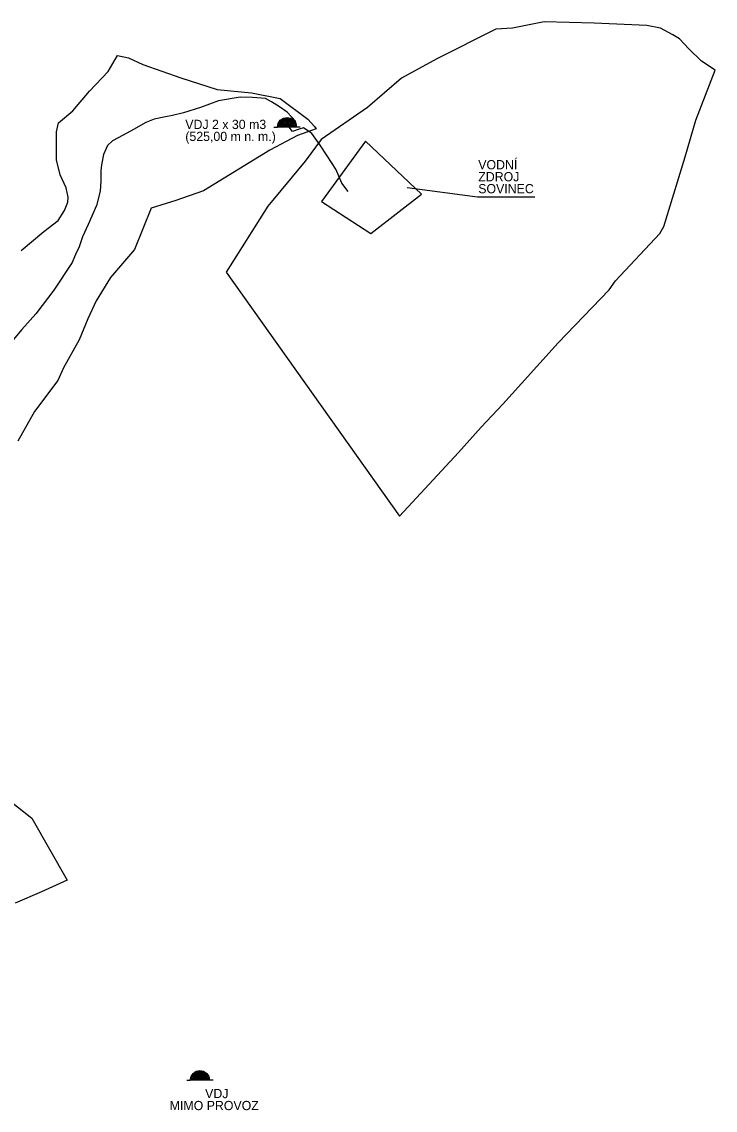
# Model space of a CAD drawing. Extents: x -547132 to -534149, y -1095664 to -1090118.
# Drawn here: x -544078 to -543326, y -1094606 to -1093426 of the extents above; entities that cross this region are included whole.
import ezdxf

# ---------------------------------------------------------------- set-up
doc = ezdxf.new("R2010")
doc.units = 0
for name, color, linetype in [('Vrstva 15', 7, 'Continuous'), ('Vrstva 3', 7, 'Continuous'), ('Vrstva 54', 7, 'Continuous'), ('Vrstva 55', 7, 'Continuous'), ('Vrstva 56', 7, 'Continuous')]:
    doc.layers.add(name, color=color, linetype=linetype)

msp = doc.modelspace()

# ---------------------------------------------------------------- linework, layer by layer
at = {"layer": 'Vrstva 15'}
for p, q in [((-543804.9, -1093540.2), (-543801, -1093540.2)), ((-543776.1, -1093540.2), (-543780.1, -1093540.2)), ((-543899.3, -1094573.8), (-543895.4, -1094573.8)), ((-543870.5, -1094573.8), (-543874.5, -1094573.8))]:
    msp.add_line(p, q, dxfattribs=at)
for points in [[(-543801, -1093540.2), (-543800.2, -1093536.2), (-543797.9, -1093532.8), (-543794.5, -1093530.6), (-543790.5, -1093529.8), (-543786.5, -1093530.6), (-543783.1, -1093532.8), (-543780.9, -1093536.2), (-543780.1, -1093540.2)], [(-543799.7, -1093539.2), (-543799.2, -1093536.6), (-543797.2, -1093533.6), (-543794.1, -1093531.5), (-543790.5, -1093530.8), (-543786.9, -1093531.5), (-543783.8, -1093533.6), (-543781.8, -1093536.6), (-543781.3, -1093539.2)], [(-543798.5, -1093538.2), (-543798.3, -1093537), (-543796.5, -1093534.3), (-543793.7, -1093532.4), (-543790.5, -1093531.8), (-543787.3, -1093532.4), (-543784.6, -1093534.3), (-543782.7, -1093537), (-543782.5, -1093538.2)], [(-543797.2, -1093537.2), (-543795.7, -1093535), (-543793.3, -1093533.4), (-543790.5, -1093532.8), (-543787.7, -1093533.4), (-543785.3, -1093535), (-543783.8, -1093537.2)], [(-543795.4, -1093536.2), (-543795, -1093535.7), (-543792.9, -1093534.3), (-543790.5, -1093533.8), (-543788.1, -1093534.3), (-543786, -1093535.7), (-543785.7, -1093536.2)], [(-543792.3, -1093535.2), (-543790.5, -1093534.9), (-543788.7, -1093535.2)], [(-543895.4, -1094573.8), (-543894.6, -1094569.8), (-543892.3, -1094566.4), (-543888.9, -1094564.2), (-543884.9, -1094563.4), (-543880.9, -1094564.2), (-543877.6, -1094566.4), (-543875.3, -1094569.8), (-543874.5, -1094573.8)], [(-543894.2, -1094572.8), (-543893.7, -1094570.2), (-543891.6, -1094567.2), (-543888.5, -1094565.1), (-543884.9, -1094564.4), (-543881.3, -1094565.1), (-543878.3, -1094567.2), (-543876.2, -1094570.2), (-543875.7, -1094572.8)], [(-543893, -1094571.8), (-543892.7, -1094570.6), (-543890.9, -1094567.9), (-543888.2, -1094566.1), (-543884.9, -1094565.4), (-543881.7, -1094566.1), (-543879, -1094567.9), (-543877.2, -1094570.6), (-543876.9, -1094571.8)], [(-543891.7, -1094570.8), (-543890.2, -1094568.6), (-543887.8, -1094567), (-543884.9, -1094566.4), (-543882.1, -1094567), (-543879.7, -1094568.6), (-543878.2, -1094570.8)], [(-543889.8, -1094569.8), (-543889.4, -1094569.3), (-543887.4, -1094567.9), (-543884.9, -1094567.5), (-543882.5, -1094567.9), (-543880.4, -1094569.3), (-543880.1, -1094569.8)], [(-543886.7, -1094568.8), (-543884.9, -1094568.5), (-543883.2, -1094568.8)]]:
    msp.add_lwpolyline(points, close=True, dxfattribs=at)
at = {"layer": 'Vrstva 3'}
for points in [[(-543783.5, -1093536.2), (-543781.1, -1093534), (-543790.2, -1093524.2), (-543798.7, -1093518.4), (-543807.5, -1093512.9), (-543814, -1093509.3), (-543827.9, -1093508.1), (-543841.3, -1093507.8), (-543864.9, -1093511.9), (-543874.6, -1093515.5), (-543884.2, -1093518.9), (-543902.9, -1093524.9), (-543914.7, -1093527.8), (-543922.4, -1093529), (-543934.4, -1093531.6), (-543943.7, -1093535.4), (-543957, -1093542.7), (-543968.2, -1093548.9), (-543979.9, -1093555.3), (-543985, -1093560.3), (-543989.5, -1093570.1), (-543991.7, -1093581.3), (-543992.2, -1093587.6), (-543992.2, -1093598.8), (-543993, -1093609.7), (-543997.2, -1093625.1), (-544006.2, -1093645.7), (-544012.1, -1093659.4), (-544016.2, -1093671.3), (-544019, -1093676.5), (-544023.4, -1093687.2), (-544043.3, -1093716.9), (-544062.7, -1093742.9), (-544078.1, -1093759.8)], [(-543783.5, -1093536.2), (-543781.1, -1093534), (-543790.2, -1093524.2), (-543798.7, -1093518.4), (-543807.5, -1093512.9), (-543814, -1093509.3), (-543827.9, -1093508.1), (-543841.3, -1093507.8), (-543864.9, -1093511.9), (-543874.6, -1093515.5), (-543884.2, -1093518.9), (-543902.9, -1093524.9), (-543914.7, -1093527.8), (-543922.4, -1093529), (-543934.4, -1093531.6), (-543943.7, -1093535.4), (-543957, -1093542.7), (-543968.2, -1093548.9), (-543979.9, -1093555.3), (-543985, -1093560.3), (-543989.5, -1093570.1), (-543991.7, -1093581.3), (-543992.2, -1093587.6), (-543992.2, -1093598.8), (-543993, -1093609.7), (-543997.2, -1093625.1), (-544006.2, -1093645.7), (-544012.1, -1093659.4), (-544016.2, -1093671.3), (-544019, -1093676.5), (-544023.4, -1093687.2), (-544043.3, -1093716.9), (-544062.7, -1093742.9), (-544078.1, -1093759.8)], [(-543724.3, -1093610.2), (-543731, -1093601.2), (-543737.6, -1093586), (-543746.9, -1093571.3), (-543754.6, -1093559.7), (-543763.5, -1093547), (-543772.6, -1093541), (-543777.5, -1093542.3), (-543784.6, -1093545.1), (-543788.1, -1093540.3)], [(-543724.3, -1093610.2), (-543731, -1093601.2), (-543737.6, -1093586), (-543746.9, -1093571.3), (-543754.6, -1093559.7), (-543763.5, -1093547), (-543772.6, -1093541), (-543777.5, -1093542.3), (-543784.6, -1093545.1), (-543788.1, -1093540.3)], [(-544078.1, -1093759.8), (-544096.7, -1093782), (-544120.8, -1093818.9), (-544135.7, -1093837.7), (-544160.8, -1093868.2), (-544170, -1093877.9), (-544188.5, -1093891.9), (-544202.8, -1093903.2), (-544216.3, -1093916.1), (-544238.9, -1093943.2), (-544254, -1093962.7), (-544263.4, -1093977.3), (-544284.6, -1094008), (-544299.8, -1094026.6), (-544307.5, -1094035.3), (-544316.2, -1094045.5), (-544341.9, -1094072.9), (-544346.8, -1094078.5)], [(-544078.1, -1093759.8), (-544096.7, -1093782), (-544120.8, -1093818.9), (-544135.7, -1093837.7), (-544160.8, -1093868.2), (-544170, -1093877.9), (-544188.5, -1093891.9), (-544202.8, -1093903.2), (-544216.3, -1093916.1), (-544238.9, -1093943.2), (-544254, -1093962.7), (-544263.4, -1093977.3), (-544284.6, -1094008), (-544299.8, -1094026.6), (-544307.5, -1094035.3), (-544316.2, -1094045.5), (-544341.9, -1094072.9), (-544346.8, -1094078.5)]]:
    msp.add_lwpolyline(points, dxfattribs=at)
at = {"layer": 'Vrstva 54'}
for points in [[(-544078.6, -1093674), (-544054.1, -1093653.3), (-544038.8, -1093641.5), (-544031.7, -1093630.7), (-544028.1, -1093621.6), (-544027.9, -1093616.1), (-544030, -1093606.1), (-544036.4, -1093592.1), (-544040.5, -1093575.9), (-544040.5, -1093545.4), (-544038.2, -1093535.6), (-544022.6, -1093522.7), (-544004.6, -1093501.3), (-543984.3, -1093480), (-543974.3, -1093462.4), (-543962.2, -1093465.1), (-543946.7, -1093472.4), (-543905.7, -1093486.8), (-543866.3, -1093499.4), (-543829.2, -1093503.2), (-543797.9, -1093509.3), (-543767.8, -1093531.6), (-543760.7, -1093539.4), (-543759, -1093542), (-543779.2, -1093549.2), (-543809.3, -1093565.4), (-543880.9, -1093609.5), (-543911.2, -1093619.7), (-543937.8, -1093628), (-543956, -1093672.8), (-543981.8, -1093703.4), (-543997.4, -1093728.7), (-544006.3, -1093748.2), (-544015.8, -1093771.1), (-544032.7, -1093801.3), (-544039, -1093815.1), (-544064.2, -1093848.7), (-544082.3, -1093880.9)], [(-544107.3, -1094258.3), (-544067.1, -1094289.8), (-544028.8, -1094356.9), (-544056.6, -1094369.4), (-544085.4, -1094381.8)]]:
    msp.add_lwpolyline(points, dxfattribs=at)
at = {"layer": 'Vrstva 55'}
msp.add_lwpolyline([(-543644.7, -1093613.1), (-543705.6, -1093555.6), (-543753.3, -1093620.9), (-543699.6, -1093655.7)], close=True, dxfattribs=at)
at = {"layer": 'Vrstva 56'}
msp.add_lwpolyline([(-543347.4, -1093532.8), (-543326.3, -1093478.4), (-543341.1, -1093468.8), (-543354.8, -1093455.4), (-543364.9, -1093444.6), (-543372.2, -1093440.1), (-543385.7, -1093433.1), (-543400.4, -1093430), (-543457.7, -1093427.4), (-543511.8, -1093426), (-543546.1, -1093433), (-543564, -1093433.9), (-543628.2, -1093466.1), (-543666.4, -1093487.2), (-543703.3, -1093519.1), (-543753.6, -1093553.5), (-543770.8, -1093577.1), (-543811.3, -1093626.1), (-543856.5, -1093697.4), (-543668.6, -1093962.3), (-543604.6, -1093893), (-543580, -1093865.5), (-543556.7, -1093840.7), (-543536.4, -1093818.4), (-543496.5, -1093774.3), (-543441.2, -1093716.7), (-543434.6, -1093707.1), (-543386.5, -1093655.5), (-543382.2, -1093648.1), (-543358.8, -1093572.4)], close=True, dxfattribs=at)
msp.add_lwpolyline([(-543660.4, -1093605.8), (-543584.1, -1093615.7), (-543522, -1093615.7)], dxfattribs=at)

# ---------------------------------------------------------------- texts
at = {"layer": 'Vrstva 15'}
for s, p in [('VDJ 2 x 30 m3', (-543900.8, -1093542.3)), ('(525,00 m n. m.)', (-543900.8, -1093555.3)), ('VDJ', (-543879.3, -1094593.3)), ('MIMO PROVOZ', (-543917.7, -1094606.3))]:
    msp.add_text(s, height=10, dxfattribs=at).set_placement(p)
at = {"layer": 'Vrstva 56'}
for s, p in [('VODNÍ', (-543583.2, -1093586)), ('ZDROJ', (-543583.2, -1093599)), ('SOVINEC', (-543583.2, -1093612))]:
    msp.add_text(s, height=10, dxfattribs=at).set_placement(p)

doc.saveas('drawing.dxf')
